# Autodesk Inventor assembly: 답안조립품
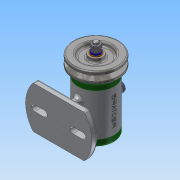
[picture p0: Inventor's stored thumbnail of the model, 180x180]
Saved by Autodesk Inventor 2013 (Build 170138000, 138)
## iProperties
Created: 2017-12
Part Number: 답안조립품
Document SubType Name: Assembly
Designer: Administrator
Author: Administrator
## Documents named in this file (14)
- C:\Users\Administrator\Desktop\471208V1008\답안조립품.iam
- C:\Users\Administrator\Desktop\471208V1008\본체.ipt
- C:\Users\Administrator\Desktop\471208V1008\V벨트풀리.ipt
- C:\Users\Administrator\Desktop\471208V1008\고무캡.ipt
- C:\Users\Administrator\Desktop\471208V1008\너트 M 8.ipt
- C:\Users\Administrator\Desktop\471208V1008\뒤커버.ipt
- C:\Users\Administrator\Desktop\471208V1008\베어링 15 x 32 x 9.ipt
- C:\Users\Administrator\Desktop\471208V1008\볼트 M4 x 12.ipt
- C:\Users\Administrator\Desktop\471208V1008\스프링와셔 8.ipt
- C:\Users\Administrator\Desktop\471208V1008\앞커버.ipt
- C:\Users\Administrator\Desktop\471208V1008\오일 실 15 25 7.ipt
- C:\Users\Administrator\Desktop\471208V1008\와셔 8x17.ipt
- C:\Users\Administrator\Desktop\471208V1008\축.ipt
- C:\Users\Administrator\Desktop\471208V1008\키 3 x 3 x 12.ipt
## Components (2 placed, 2 different names)
1. V벨트풀리:1
2. 고무캡:1
